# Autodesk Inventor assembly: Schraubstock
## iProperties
Created: 2009-10
Part Number: Schraubstock
Description: Startmodell Baugruppe
Document SubType Name: Assembly
Designer: BoseDa
Company: Grenzebach BSH
Author: BoseDa
